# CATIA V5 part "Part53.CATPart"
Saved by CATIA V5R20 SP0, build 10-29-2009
Part number: FA 042200-1
Revision: ANY
Definition: UNKNOWN
Nomenclature: FA 042200-1
Source: Unknown
Bounding box of the stored display mesh (mm): x 0.374 to 3.8, y -1.58 to 1.58, z -1.58 to 1.58
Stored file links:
  C:\Users\Utente\Desktop\IO LAVORO\3D X SITO CF\CUMSA\3D files FA\FA 042204-21\Part53.CATPart

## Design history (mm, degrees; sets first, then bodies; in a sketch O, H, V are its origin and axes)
Body1 "Cortar-Extruir2" (main body)
  Solid1: solid without history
